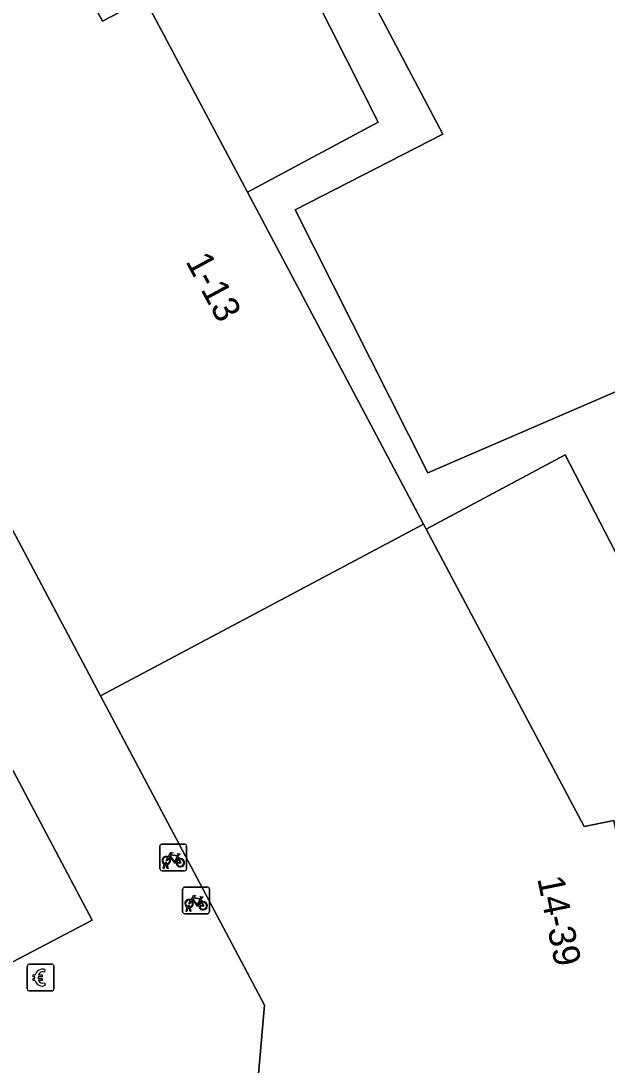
# Model space of a CAD drawing. Extents: x 160304 to 160955, y 383684 to 384161.
# Drawn here: x 160842.1 to 160864.04, y 383855.78 to 383894.83 of the extents above; entities that cross this region are included whole.
import ezdxf

# ---------------------------------------------------------------- set-up
doc = ezdxf.new("R2010")
doc.units = 0
for name, color, linetype in [('IMGEO_Betaalautomaat', 7, 'Continuous'), ('IMGEO_Erf', 7, 'Continuous'), ('IMGEO_Fietsenrek', 7, 'Continuous'), ('IMGEO_Groenvoorziening', 7, 'Continuous'), ('IMGEO_Pand', 7, 'Continuous'), ('IMGEO_Pand_nummerreeks', 7, 'Continuous'), ('IMGEO_Parkeervlak_open', 7, 'Continuous'), ('IMGEO_Voetpad_open', 7, 'Continuous')]:
    doc.layers.add(name, color=color, linetype=linetype)

msp = doc.modelspace()

# ---------------------------------------------------------------- linework, layer by layer
at = {"layer": 'IMGEO_Betaalautomaat'}
for p, q in [((160842.341, 383858.628), (160842.341, 383859.469)), ((160842.341, 383859.469), (160842.341, 383858.628)), ((160842.416, 383859.552), (160843.257, 383859.552)), ((160843.257, 383859.552), (160842.416, 383859.552)), ((160843.003, 383859.357), (160842.986, 383859.257)), ((160843.34, 383859.478), (160843.34, 383858.637)), ((160843.34, 383858.637), (160843.34, 383859.478)), ((160842.624, 383859.016), (160842.624, 383859.084)), ((160842.745, 383859.084), (160842.745, 383859.016)), ((160842.99, 383858.851), (160843.012, 383858.764)), ((160843.266, 383858.553), (160842.425, 383858.553)), ((160842.425, 383858.553), (160843.266, 383858.553))]:
    msp.add_line(p, q, dxfattribs=at)
for points in [[(160842.624, 383859.084), (160842.555, 383859.084), (160842.555, 383859.153), (160842.634, 383859.153)], [(160842.629, 383858.947), (160842.555, 383858.947), (160842.555, 383859.016), (160842.624, 383859.016)], [(160842.756, 383859.153), (160842.903, 383859.153), (160842.903, 383859.084), (160842.745, 383859.084)], [(160842.745, 383859.016), (160842.903, 383859.016), (160842.903, 383858.947), (160842.759, 383858.947)]]:
    msp.add_lwpolyline(points, dxfattribs=at)
for centre, radius, start, end in [((160842.419, 383859.475), 0.0779, 92.4484, 184.2845), ((160842.419, 383859.475), 0.0779, 92.4484, 184.2845), ((160842.917, 383859.077), 0.293, 73.014, 165.0139), ((160842.923, 383859.09), 0.179, 69.3236, 159.5683), ((160843.263, 383859.475), 0.0779, 2.4484, 94.2845), ((160843.263, 383859.475), 0.0779, 2.4484, 94.2845), ((160842.89, 383859.002), 0.267, 191.8096, 297.0389), ((160842.923, 383859.017), 0.179, 202.7625, 291.8693), ((160842.419, 383858.631), 0.0779, 182.4484, 274.2845), ((160842.419, 383858.631), 0.0779, 182.4484, 274.2845), ((160843.263, 383858.631), 0.0779, 272.4484, 4.2845), ((160843.263, 383858.631), 0.0779, 272.4484, 4.2845)]:
    msp.add_arc(centre, radius, start, end, dxfattribs=at)
at = {"layer": 'IMGEO_Erf'}
for points in [[(160855.478, 383891.046), (160848.942, 383903.988), (160842.207, 383900.37), (160845.158, 383894.814), (160846.741, 383895.654), (160850.579, 383888.426)], [(160867.154, 383826.483), (160870.895, 383862.33), (160862.472, 383878.595), (160857.274, 383875.816), (160863.179, 383864.695), (160864.295, 383864.926), (160865.99, 383856.743), (160864.863, 383856.51), (160863.738, 383843.778), (160862.62, 383831.129), (160863.763, 383830.681), (160860.673, 383822.784), (160859.69, 383823.168), (160851.843, 383813.196), (160854.767, 383810.821)]]:
    msp.add_lwpolyline(points, close=True, dxfattribs=at)
at = {"layer": 'IMGEO_Fietsenrek'}
for p, q in [((160847.303, 383863.121), (160847.303, 383863.962)), ((160847.303, 383863.962), (160847.303, 383863.121)), ((160847.378, 383864.046), (160848.219, 383864.046)), ((160848.219, 383864.046), (160847.378, 383864.046)), ((160848.303, 383863.971), (160848.303, 383863.13)), ((160848.303, 383863.13), (160848.303, 383863.971)), ((160847.99, 383863.595), (160848.026, 383863.5)), ((160847.43, 383863.13), (160847.469, 383863.29)), ((160847.464, 383863.13), (160847.43, 383863.13)), ((160847.499, 383863.278), (160847.464, 383863.13)), ((160847.541, 383863.302), (160847.54, 383863.306)), ((160847.582, 383863.13), (160847.548, 383863.272)), ((160847.572, 383863.313), (160847.573, 383863.306)), ((160847.58, 383863.276), (160847.615, 383863.13)), ((160847.615, 383863.13), (160847.582, 383863.13)), ((160848.228, 383863.046), (160847.387, 383863.046)), ((160847.387, 383863.046), (160848.228, 383863.046)), ((160848.156, 383861.513), (160848.156, 383862.354)), ((160848.156, 383862.354), (160848.156, 383861.513)), ((160848.231, 383862.438), (160849.072, 383862.438)), ((160849.072, 383862.438), (160848.231, 383862.438)), ((160849.156, 383862.363), (160849.156, 383861.522)), ((160849.156, 383861.522), (160849.156, 383862.363)), ((160848.843, 383861.987), (160848.879, 383861.892)), ((160848.283, 383861.522), (160848.322, 383861.682)), ((160848.352, 383861.67), (160848.317, 383861.522)), ((160848.394, 383861.694), (160848.393, 383861.698)), ((160848.435, 383861.522), (160848.401, 383861.664)), ((160848.425, 383861.705), (160848.426, 383861.698)), ((160848.433, 383861.668), (160848.468, 383861.522)), ((160849.081, 383861.438), (160848.24, 383861.438)), ((160848.24, 383861.438), (160849.081, 383861.438)), ((160848.317, 383861.522), (160848.283, 383861.522)), ((160848.468, 383861.522), (160848.435, 383861.522))]:
    msp.add_line(p, q, dxfattribs=at)
for points in [[(160847.637, 383863.52), (160847.585, 383863.43), (160847.545, 383863.405), (160847.546, 383863.452), (160847.601, 383863.546)], [(160847.616, 383863.572), (160847.711, 383863.736), (160847.797, 383863.722), (160847.799, 383863.713), (160847.743, 383863.702), (160847.716, 383863.657), (160847.972, 383863.616)], [(160847.912, 383863.328), (160847.862, 383863.328), (160847.671, 383863.579), (160847.652, 383863.547)], [(160847.959, 383863.591), (160847.702, 383863.632), (160847.685, 383863.603), (160847.852, 383863.383), (160847.959, 383863.591)], [(160848.007, 383863.493), (160847.977, 383863.57), (160847.868, 383863.352), (160847.911, 383863.352)], [(160847.972, 383863.616), (160847.997, 383863.665), (160847.991, 383863.669), (160847.968, 383863.673), (160847.956, 383863.68), (160847.955, 383863.683), (160847.957, 383863.688), (160848.052, 383863.673), (160848.054, 383863.663), (160848.044, 383863.65), (160848.032, 383863.644), (160848.018, 383863.65), (160847.99, 383863.595)], [(160847.941, 383863.352), (160848.061, 383863.351), (160848.017, 383863.465)], [(160848.037, 383863.472), (160848.092, 383863.327), (160847.942, 383863.327)], [(160848.49, 383861.912), (160848.438, 383861.822), (160848.398, 383861.797), (160848.399, 383861.844), (160848.454, 383861.938)], [(160848.469, 383861.964), (160848.564, 383862.128), (160848.65, 383862.114), (160848.652, 383862.105), (160848.596, 383862.094), (160848.569, 383862.049), (160848.825, 383862.008)], [(160848.765, 383861.72), (160848.715, 383861.72), (160848.524, 383861.971), (160848.505, 383861.939)], [(160848.812, 383861.983), (160848.555, 383862.024), (160848.538, 383861.995), (160848.705, 383861.775), (160848.812, 383861.983)], [(160848.86, 383861.885), (160848.83, 383861.962), (160848.721, 383861.744), (160848.764, 383861.744)], [(160848.825, 383862.008), (160848.85, 383862.057), (160848.844, 383862.061), (160848.821, 383862.065), (160848.809, 383862.072), (160848.808, 383862.075), (160848.81, 383862.08), (160848.905, 383862.065), (160848.907, 383862.055), (160848.897, 383862.042), (160848.885, 383862.036), (160848.871, 383862.042), (160848.843, 383861.987)], [(160848.794, 383861.744), (160848.914, 383861.743), (160848.87, 383861.857)], [(160848.89, 383861.864), (160848.945, 383861.719), (160848.795, 383861.719)]]:
    msp.add_lwpolyline(points, dxfattribs=at)
for centre, radius, start, end in [((160847.381, 383863.968), 0.0779, 92.4484, 184.2845), ((160847.381, 383863.968), 0.0779, 92.4484, 184.2845), ((160848.225, 383863.968), 0.0779, 2.4484, 94.2845), ((160848.225, 383863.968), 0.0779, 2.4484, 94.2845), ((160847.543, 383863.431), 0.159, 62.6766, 242.1369), ((160847.543, 383863.431), 0.129, 63.3192, 238.903), ((160847.543, 383863.431), 0.129, 283.6043, 43.4302), ((160847.543, 383863.431), 0.159, 283.5766, 46.6042), ((160848.07, 383863.347), 0.159, 113.3408, 178.3217), ((160848.07, 383863.347), 0.159, 187.0065, 105.7708), ((160847.381, 383863.124), 0.0779, 182.4484, 274.2845), ((160847.381, 383863.124), 0.0779, 182.4484, 274.2845), ((160847.523, 383863.302), 0.0499, 12.8025, 158.6934), ((160847.543, 383863.431), 0.159, 253.9967, 271.7867), ((160847.523, 383863.302), 0.0174, 12.8025, 163.4502), ((160847.543, 383863.431), 0.129, 253.415, 269.0204), ((160848.07, 383863.347), 0.129, 113.923, 177.9556), ((160848.07, 383863.347), 0.129, 188.6715, 104.5883), ((160848.225, 383863.124), 0.0779, 272.4484, 4.2845), ((160848.225, 383863.124), 0.0779, 272.4484, 4.2845), ((160848.234, 383862.36), 0.0779, 92.4484, 184.2845), ((160848.234, 383862.36), 0.0779, 92.4484, 184.2845), ((160849.078, 383862.36), 0.0779, 2.4484, 94.2845), ((160849.078, 383862.36), 0.0779, 2.4484, 94.2845), ((160848.396, 383861.823), 0.159, 62.6766, 242.1369), ((160848.396, 383861.823), 0.129, 63.3192, 238.903), ((160848.396, 383861.823), 0.159, 283.5766, 46.6042), ((160848.376, 383861.694), 0.0499, 12.8025, 158.6934), ((160848.396, 383861.823), 0.159, 253.9967, 271.7867), ((160848.376, 383861.694), 0.0174, 12.8025, 163.4502), ((160848.396, 383861.823), 0.129, 253.415, 269.0204), ((160848.396, 383861.823), 0.129, 283.6043, 43.4302), ((160848.923, 383861.739), 0.159, 113.3408, 178.3217), ((160848.923, 383861.739), 0.159, 187.0065, 105.7708), ((160848.923, 383861.739), 0.129, 113.923, 177.9556), ((160848.923, 383861.739), 0.129, 188.6715, 104.5883), ((160848.234, 383861.516), 0.0779, 182.4484, 274.2845), ((160848.234, 383861.516), 0.0779, 182.4484, 274.2845), ((160849.078, 383861.516), 0.0779, 272.4484, 4.2845), ((160849.078, 383861.516), 0.0779, 272.4484, 4.2845)]:
    msp.add_arc(centre, radius, start, end, dxfattribs=at)
at = {"layer": 'IMGEO_Groenvoorziening'}
for points in [[(160859.24, 383908.453), (160856.39, 383907.451), (160851.446, 383905.29), (160850.413, 383904.764), (160857.898, 383890.588), (160852.372, 383887.768), (160857.334, 383877.933), (160869.118, 383883.019), (160866.077, 383895.016)], [(160869.118, 383883.019), (160857.334, 383877.933), (160852.372, 383887.768), (160857.898, 383890.588), (160850.413, 383904.764), (160849.912, 383904.509), (160848.942, 383903.988), (160855.478, 383891.046), (160850.579, 383888.426), (160857.172, 383876.008), (160857.274, 383875.816), (160862.472, 383878.595), (160870.895, 383862.33)]]:
    msp.add_lwpolyline(points, dxfattribs=at)
at = {"layer": 'IMGEO_Pand'}
for points in [[(160857.172, 383876.008), (160850.579, 383888.426), (160846.741, 383895.654), (160845.158, 383894.814), (160842.207, 383900.37), (160831.698, 383894.79), (160835.078, 383888.424), (160845.08, 383869.587)], [(160857.172, 383876.008), (160845.08, 383869.587), (160851.22, 383858.023), (160850.918, 383854.597), (160850.344, 383854.648), (160847.603, 383853.097), (160846.911, 383845.265), (160863.738, 383843.778), (160864.863, 383856.51), (160865.99, 383856.743), (160864.295, 383864.926), (160863.179, 383864.695), (160857.274, 383875.816)]]:
    msp.add_lwpolyline(points, close=True, dxfattribs=at)
at = {"layer": 'IMGEO_Parkeervlak_open'}
msp.add_lwpolyline([(160841.141, 383858.403), (160841.146, 383858.446), (160841.177, 383858.614), (160841.222, 383858.778), (160841.282, 383858.938), (160841.356, 383859.092), (160841.444, 383859.239), (160841.544, 383859.377), (160841.656, 383859.506), (160841.779, 383859.624), (160844.764, 383861.196), (160833.041, 383883.331), (160829.832, 383881.61), (160829.033, 383881.187)], close=True, dxfattribs=at)
at = {"layer": 'IMGEO_Voetpad_open'}
for points in [[(160850.918, 383854.597), (160851.22, 383858.023), (160845.08, 383869.587), (160835.078, 383888.424)], [(160833.041, 383883.331), (160844.764, 383861.196), (160841.779, 383859.624)]]:
    msp.add_lwpolyline(points, dxfattribs=at)

# ---------------------------------------------------------------- texts
at = {"layer": 'IMGEO_Pand_nummerreeks'}
for s, rotation, p in [('1-13', 298.3234, (160848.248, 383885.839)), ('14-39', 281.5301, (160861.425, 383862.759))]:
    msp.add_text(s, height=1, rotation=rotation, dxfattribs=at).set_placement(p)

doc.saveas('drawing.dxf')
